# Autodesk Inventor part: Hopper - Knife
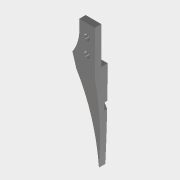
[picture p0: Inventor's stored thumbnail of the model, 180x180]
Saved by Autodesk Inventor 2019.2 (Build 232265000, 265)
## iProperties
Created: 2005-11
Part Number: Hopper - Knife
Document SubType Name: Modeling
Designer: floress
Material: Stainless Steel
Density: 8 g/cm^3
Appearance: Semi-Polished
Mass: 11.798 g
Surface Area: 13.7269 cm^2
Volume: 1.47475 cm^3
Author: floress
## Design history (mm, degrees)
sketch "Sketch1"
  geometry: L1 (34.809, 30.74)-(34.809, 49.241); L2 (34.809, 49.241)-(27.035, 49.241); L3 (27.035, 49.241)-(27.035, 43.123); L4 (51.39, 45.213)-(51.39, -16.05) reference; L5 (27.093, 30.74)-(34.809, 30.74) reference; L6 (34.809, 30.74)-(34.809, 92.838) reference; L7 (26.468, 92.838)-(34.809, 92.838) reference; L8 (26.468, 50.312)-(26.468, 92.838) reference; L9 (65.217, 48.707)-(65.217, -16.05) reference; C1 r 1.778 at (-10.983, -19.225) reference; C2 r 1.778 at (-10.983, -12.875) reference; C3 r 44.45 at (-10.983, -16.05) reference; C4 r 1.778 at (30.951, 43.123); C5 r 1.778 at (30.951, 35.503); C6 r 1.422 at (62.042, 35.688) reference; C7 r 1.74 at (58.303, 0.763) reference; C8 r 1.74 at (58.303, 26.163) reference; C9 r 1.593 at (-10.983, 49.992) reference; C10 r 1.593 at (-10.983, -82.092) reference; C11 r 1.422 at (22.038, 41.144) reference; C12 r 1.422 at (55.059, -16.05) reference; C13 r 1.422 at (22.038, -73.244) reference; C14 r 1.422 at (46.211, -49.071) reference; C15 r 1.422 at (30.951, 35.503) reference; C16 r 1.422 at (30.951, 43.123) reference; A1 r 860.911 centre (-826.103, 30.74) between (33.678, -13.364) and (34.809, 30.74); A2 r 20.657 centre (6.456, 44.916) between (23.594, 33.383) and (27.035, 43.123); A3 r 255.276 centre (-219.802, -43.585) between (33.678, -13.364) and (23.594, 33.383); A4 r 3.175 centre (51.39, 48.388) between (51.39, 45.213) and (53.43, 45.956) reference; A5 r 61.349 centre (-9.959, -16.05) between (-71.308, -16.05) and (51.39, -16.05) reference; A6 r 60.325 centre (-10.983, -16.05) between (27.093, 30.74) and (-71.308, -16.05) reference; A7 r 76.2 centre (-10.983, -16.05) between (26.468, 50.312) and (23.547, 51.877) reference; A8 r 3.175 centre (22.109, 49.047) between (20.67, 46.217) and (23.547, 51.877) reference; A9 r 69.85 centre (-10.983, -16.05) between (20.67, 46.217) and (58.801, -19.087) reference; A10 r 3.175 centre (61.973, -19.225) between (65.145, -19.363) and (58.801, -19.087) reference; A11 r 76.2 centre (-10.983, -16.05) between (65.145, -19.363) and (65.217, -16.05) reference; A12 r 13.4 centre (62.042, 35.688) between (65.217, 48.707) and (53.43, 45.956) reference
  constraints: 6 end point, 6 point on circle, 5 centre point, 2 perpendicular, 2 tangent, 1 equal radius
  dimensions: "d0" = 3.556 diameter of C4
extrude "Extrusion1" new body sketch "Sketch1" distance "d1" = 3.175; taper "d2" = 0 deg
sketch "Sketch2"
  geometry: L1 (-34.809, 30.74)-(-27.093, 30.74); L2 (-27.093, 30.74)-(-23.594, 33.383); A1 r 255.276 centre (219.802, -43.585) between (-33.678, -13.364) and (-23.594, 33.383) reference; A2 r 255.276 centre (219.802, -43.585) between (-23.594, 33.383) and (-33.678, -13.364); A3 r 860.911 centre (826.103, 30.74) between (-34.809, 30.74) and (-33.678, -13.364); A4 r 860.911 centre (826.103, 30.74) between (-33.678, -13.364) and (-34.809, 30.74) reference
  constraints: 4 end point, 4 point on circle, 3 concentric, 2 centre point
extrude "Extrusion2" join sketch "Sketch2" distance "d3" = 3.175; taper "d4" = 0 deg
sketch "Sketch3"
  geometry: L1 (-13.364, 0)-(-13.364, 3.175); L2 (-13.364, 3.175)-(26.93, 3.175); A1 r 182.131 centre (-7.435, 182.035) between (-13.364, 0) and (26.93, 3.175)
  constraints: 4 end point, 2 point on circle, 1 centre point, 1 perpendicular
extrude "Extrusion3" cut sketch "Sketch3" extent not by distance; stored distance "d6" = 3.175; taper "d7" = 0 deg
sketch "Sketch4"
  geometry: C1 r 7.144 at (10.983, -16.05) reference; A1 r 860.911 centre (826.103, 30.74) between (-34.809, 30.74) and (-33.678, -13.364) reference; A2 r 255.276 centre (219.802, -43.585) between (-23.594, 33.383) and (-33.678, -13.364) reference; A3 r 54.86 centre (10.983, -16.05) between (-26.314, 24.181) and (-34.653, 14.395); A4 r 52.955 centre (10.983, -16.05) between (-27.284, 20.553) and (-34.581, 10.934)
  constraints: 8 point on circle, 2 centre point, 2 coincident
extrude "Extrusion4" cut sketch "Sketch4" distance "d9" = 1.5875; taper "d10" = 0 deg
sketch "Sketch5"
  geometry: L1 (27.035, 43.123)-(27.035, 49.241) reference; L2 (27.035, 49.241)-(34.809, 49.241) reference; L3 (34.809, 49.241)-(34.809, 30.74) reference; A1 r 20.657 centre (6.456, 44.916) between (23.594, 33.383) and (27.035, 43.123) reference; A2 r 860.911 centre (-826.103, 30.74) between (34.8, 26.93) and (34.809, 30.74) reference; A3 r 255.276 centre (-219.802, -43.585) between (25.541, 26.93) and (23.594, 33.383) reference; A4 r 860.911 centre (-826.103, 30.74) between (33.678, -13.364) and (34.8, 26.93); A5 r 255.276 centre (-219.802, -43.585) between (33.678, -13.364) and (25.541, 26.93); 1 further point
  constraints: 4 point on circle, 2 centre point, 2 concentric
body "Solid1"
node "Reference2"
node "Reference7"
node "Reference8"
other parameters: "NestingThickness" = 6.35
